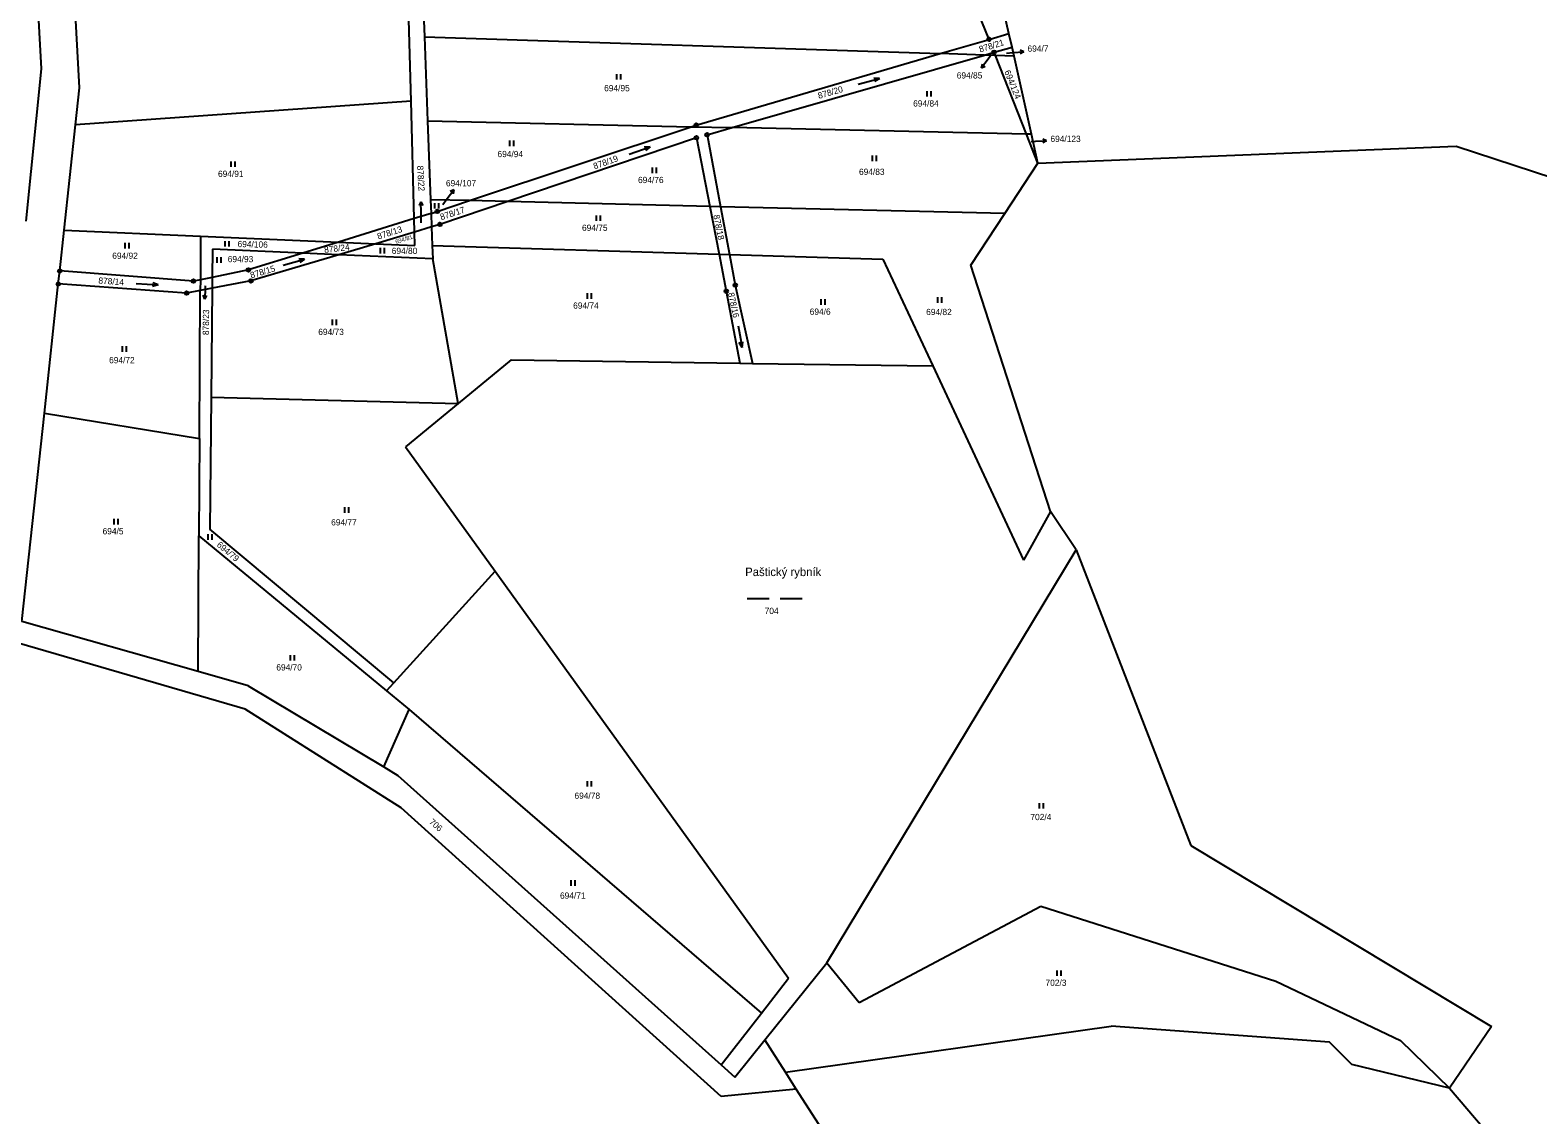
# Model space of a CAD drawing. Extents: x -791032 to -787751, y -1106872 to -1104403.
# Drawn here: x -789595.2 to -789185.3, y -1106556.6 to -1106261.6 of the extents above; entities that cross this region are included whole.
import ezdxf

# ---------------------------------------------------------------- set-up
doc = ezdxf.new("R2010")
doc.units = 0
for name, color, linetype in [('Komunikace', 7, 'Continuous'), ('Vrstva 1', 7, 'Continuous'), ('Vrstva 14', 7, 'Continuous'), ('Vrstva 16', 7, 'Continuous'), ('Vrstva 23', 7, 'Continuous'), ('Vrstva 28', 7, 'Continuous'), ('Vrstva 44', 7, 'Continuous')]:
    doc.layers.add(name, color=color, linetype=linetype)

msp = doc.modelspace()

# ---------------------------------------------------------------- linework, layer by layer
at = {"layer": 'Komunikace'}
for p, q in [((-789333.82, -1106268.19), (-789334.73, -1106269.41)), ((-789329.73, -1106267.83), (-789328.04, -1106267.68)), ((-789323.06, -1106291.82), (-789321.89, -1106291.79)), ((-789483.02, -1106308.99), (-789481.8, -1106307.36)), ((-789488.89, -1106314), (-789488.94, -1106311.25)), ((-789547.64, -1106331.08), (-789547.65, -1106331.7))]:
    msp.add_line(p, q, dxfattribs=at)
at = {"layer": 'Vrstva 1'}
for p, q in [((-789592.13, -1106272.11), (-789596.95, -1106186.19)), ((-789491.65, -1106280.87), (-789492.89, -1106234.87)), ((-789581.8, -1106277.28), (-789583.87, -1106238.77)), ((-789488.84, -1106240.8), (-789488, -1106263.4)), ((-789334.52, -1106264.06), (-789342, -1106245.55)), ((-789329.09, -1106262.43), (-789332.79, -1106245.85)), ((-789488, -1106263.4), (-789487.15, -1106286.25)), ((-789488, -1106263.4), (-789347.81, -1106267.95)), ((-789347.81, -1106267.95), (-789334.52, -1106264.06)), ((-789334.52, -1106264.06), (-789329.09, -1106262.43)), ((-789328.25, -1106266.18), (-789329.09, -1106262.43)), ((-789414.13, -1106287.36), (-789347.81, -1106267.95)), ((-789404.39, -1106288.06), (-789335.78, -1106268.34)), ((-789335.78, -1106268.34), (-789347.81, -1106267.95)), ((-789335.78, -1106268.34), (-789333.13, -1106267.58)), ((-789332.79, -1106268.44), (-789335.78, -1106268.34)), ((-789333.13, -1106267.58), (-789328.25, -1106266.18)), ((-789332.79, -1106268.44), (-789333.13, -1106267.58)), ((-789327.71, -1106268.6), (-789332.79, -1106268.44)), ((-789324.34, -1106289.81), (-789332.79, -1106268.44)), ((-789327.71, -1106268.6), (-789328.25, -1106266.18)), ((-789322.97, -1106289.84), (-789327.71, -1106268.6)), ((-789596.25, -1106313.51), (-789592.13, -1106272.11)), ((-789582.88, -1106287.34), (-789581.8, -1106277.28)), ((-789491.65, -1106280.87), (-789582.88, -1106287.34)), ((-789490.79, -1106312.81), (-789491.65, -1106280.87)), ((-789487.15, -1106286.25), (-789415.5, -1106287.82)), ((-789487.15, -1106286.25), (-789486.35, -1106307.68)), ((-789585.97, -1106315.97), (-789582.88, -1106287.34)), ((-789475.72, -1106307.94), (-789415.5, -1106287.82)), ((-789415.5, -1106287.82), (-789414.13, -1106287.36)), ((-789415.5, -1106287.82), (-789404.39, -1106288.06)), ((-789411.18, -1106290.01), (-789404.39, -1106288.06)), ((-789411.18, -1106290.01), (-789407.52, -1106309.59)), ((-789324.34, -1106289.81), (-789404.39, -1106288.06)), ((-789322.97, -1106289.84), (-789324.34, -1106289.81)), ((-789321.21, -1106297.73), (-789324.34, -1106289.81)), ((-789321.21, -1106297.73), (-789322.97, -1106289.84)), ((-789414.07, -1106290.84), (-789465.36, -1106308.19)), ((-789414.07, -1106290.84), (-789410.44, -1106309.52)), ((-789321.21, -1106297.73), (-789207.47, -1106293.12)), ((-789207.47, -1106293.12), (-789147.83, -1106312.66)), ((-789330.23, -1106311.46), (-789321.21, -1106297.73)), ((-789475.72, -1106307.94), (-789486.35, -1106307.68)), ((-789486.35, -1106307.68), (-789486.21, -1106311.44)), ((-789486.21, -1106311.44), (-789484.54, -1106310.88)), ((-789484.54, -1106310.88), (-789475.72, -1106307.94)), ((-789465.36, -1106308.19), (-789483.79, -1106314.42)), ((-789465.36, -1106308.19), (-789475.72, -1106307.94)), ((-789410.44, -1106309.52), (-789465.36, -1106308.19)), ((-789407.52, -1106309.59), (-789410.44, -1106309.52)), ((-789410.44, -1106309.52), (-789407.92, -1106322.5)), ((-789407.52, -1106309.59), (-789405.09, -1106322.58)), ((-789330.23, -1106311.46), (-789407.52, -1106309.59)), ((-789490.79, -1106312.81), (-789511.4, -1106319.2)), ((-789486.21, -1106311.44), (-789490.79, -1106312.81)), ((-789490.69, -1106316.48), (-789490.79, -1106312.81)), ((-789486.21, -1106311.44), (-789486.07, -1106315.1)), ((-789483.79, -1106314.42), (-789486.07, -1106315.1)), ((-789339.43, -1106325.47), (-789330.23, -1106311.46)), ((-789587.17, -1106327.07), (-789585.97, -1106315.97)), ((-789585.97, -1106315.97), (-789548.86, -1106317.58)), ((-789548.86, -1106317.58), (-789548.93, -1106329.45)), ((-789548.86, -1106317.58), (-789511.4, -1106319.2)), ((-789490.69, -1106316.48), (-789501.27, -1106319.64)), ((-789486.07, -1106315.1), (-789490.69, -1106316.48)), ((-789490.6, -1106320.1), (-789490.69, -1106316.48)), ((-789486.07, -1106315.1), (-789485.88, -1106320.17)), ((-789545.66, -1106321.14), (-789545.73, -1106328.8)), ((-789521.11, -1106322.21), (-789545.66, -1106321.14)), ((-789521.11, -1106322.21), (-789535.87, -1106326.78)), ((-789511.32, -1106322.64), (-789535.2, -1106329.76)), ((-789511.4, -1106319.2), (-789521.11, -1106322.21)), ((-789511.32, -1106322.64), (-789521.11, -1106322.21)), ((-789511.4, -1106319.2), (-789501.27, -1106319.64)), ((-789501.27, -1106319.64), (-789511.32, -1106322.64)), ((-789485.75, -1106323.75), (-789511.32, -1106322.64)), ((-789501.27, -1106319.64), (-789490.6, -1106320.1)), ((-789485.88, -1106320.17), (-789485.75, -1106323.75)), ((-789485.88, -1106320.17), (-789407.92, -1106322.5)), ((-789407.92, -1106322.5), (-789405.96, -1106332.56)), ((-789407.92, -1106322.5), (-789405.09, -1106322.58)), ((-789405.09, -1106322.58), (-789363.39, -1106323.83)), ((-789405.09, -1106322.58), (-789403.53, -1106330.9)), ((-789587.55, -1106330.61), (-789587.17, -1106327.07)), ((-789550.81, -1106329.83), (-789587.17, -1106327.07)), ((-789535.87, -1106326.78), (-789545.73, -1106328.8)), ((-789478.82, -1106363.09), (-789485.75, -1106323.75)), ((-789363.39, -1106323.83), (-789349.79, -1106352.91)), ((-789317.83, -1106392.51), (-789339.43, -1106325.47)), ((-789591.34, -1106365.77), (-789587.55, -1106330.61)), ((-789552.69, -1106333.07), (-789587.55, -1106330.61)), ((-789548.93, -1106329.45), (-789550.81, -1106329.83)), ((-789548.93, -1106329.45), (-789548.95, -1106332.36)), ((-789545.73, -1106328.8), (-789548.93, -1106329.45)), ((-789545.73, -1106328.8), (-789545.76, -1106331.76)), ((-789535.2, -1106329.76), (-789545.76, -1106331.76)), ((-789403.53, -1106330.9), (-789398.83, -1106352.21)), ((-789548.95, -1106332.36), (-789552.69, -1106333.07)), ((-789549.18, -1106372.68), (-789548.95, -1106332.36)), ((-789545.76, -1106331.76), (-789548.95, -1106332.36)), ((-789545.76, -1106331.76), (-789546.03, -1106361.42)), ((-789405.96, -1106332.56), (-789402.31, -1106352.16)), ((-789464.4, -1106351.28), (-789478.82, -1106363.09)), ((-789464.4, -1106351.28), (-789402.31, -1106352.16)), ((-789402.31, -1106352.16), (-789398.83, -1106352.21)), ((-789398.83, -1106352.21), (-789349.79, -1106352.91)), ((-789349.79, -1106352.91), (-789325.1, -1106405.78)), ((-789546.03, -1106361.42), (-789546.37, -1106397.29)), ((-789546.03, -1106361.42), (-789478.82, -1106363.09)), ((-789478.82, -1106363.09), (-789493.19, -1106374.87)), ((-789597.44, -1106422.43), (-789591.34, -1106365.77)), ((-789591.34, -1106365.77), (-789549.18, -1106372.68)), ((-789549.18, -1106372.68), (-789549.33, -1106399.08)), ((-789493.19, -1106374.87), (-789468.82, -1106408.7)), ((-789317.83, -1106392.51), (-789325.1, -1106405.78)), ((-789310.81, -1106402.96), (-789317.83, -1106392.51)), ((-789549.55, -1106436.02), (-789549.33, -1106399.08)), ((-789549.33, -1106399.08), (-789498.34, -1106441.3)), ((-789496.32, -1106439.07), (-789546.37, -1106397.29)), ((-789378.63, -1106515.27), (-789310.81, -1106402.96)), ((-789310.81, -1106402.96), (-789279.63, -1106483.36)), ((-789496.32, -1106439.07), (-789468.82, -1106408.7)), ((-789468.82, -1106408.7), (-789389.04, -1106519.44)), ((-789549.55, -1106436.02), (-789597.44, -1106422.43)), ((-789536.76, -1106446.28), (-789598.09, -1106428.43)), ((-789535.95, -1106439.88), (-789549.55, -1106436.02)), ((-789535.95, -1106439.88), (-789499.09, -1106462)), ((-789498.34, -1106441.3), (-789496.32, -1106439.07)), ((-789498.34, -1106441.3), (-789492.19, -1106446.4)), ((-789494.38, -1106473.09), (-789536.76, -1106446.28)), ((-789499.09, -1106462), (-789492.19, -1106446.4)), ((-789492.19, -1106446.4), (-789396.41, -1106528.93)), ((-789499.09, -1106462), (-789495.23, -1106464.32)), ((-789495.23, -1106464.32), (-789407.36, -1106543.01)), ((-789407.33, -1106551.66), (-789494.38, -1106473.09)), ((-789279.63, -1106483.36), (-789197.91, -1106532.62)), ((-789369.84, -1106526.05), (-789320.47, -1106499.9)), ((-789320.47, -1106499.9), (-789256.58, -1106520.24)), ((-789395.48, -1106536.26), (-789378.63, -1106515.27)), ((-789378.63, -1106515.27), (-789369.84, -1106526.05)), ((-789396.41, -1106528.93), (-789389.04, -1106519.44)), ((-789256.58, -1106520.24), (-789222.66, -1106536.38)), ((-789407.36, -1106543.01), (-789396.41, -1106528.93)), ((-789403.6, -1106546.38), (-789395.48, -1106536.26)), ((-789389.86, -1106545.03), (-789395.48, -1106536.26)), ((-789389.86, -1106545.03), (-789301.3, -1106532.47)), ((-789241.95, -1106536.85), (-789301.3, -1106532.47)), ((-789197.91, -1106532.62), (-789209.35, -1106549.33)), ((-789235.91, -1106542.95), (-789241.95, -1106536.85)), ((-789222.66, -1106536.38), (-789209.35, -1106549.33)), ((-789407.36, -1106543.01), (-789403.6, -1106546.38)), ((-789209.35, -1106549.33), (-789235.91, -1106542.95)), ((-789386.91, -1106549.62), (-789389.86, -1106545.03)), ((-789386.91, -1106549.62), (-789407.33, -1106551.66)), ((-789357.95, -1106594.75), (-789386.91, -1106549.62)), ((-789209.35, -1106549.33), (-789191.93, -1106569.78))]:
    msp.add_line(p, q, dxfattribs=at)
at = {"layer": 'Vrstva 16'}
for p, q in [((-789334.73, -1106269.41), (-789336.52, -1106271.817)), ((-789328.04, -1106267.68), (-789325.051, -1106267.418)), ((-789325.051, -1106267.418), (-789326.091, -1106267.007)), ((-789325.051, -1106267.418), (-789326.004, -1106268.003)), ((-789336.52, -1106271.817), (-789336.324, -1106270.716)), ((-789336.52, -1106271.817), (-789335.522, -1106271.313)), ((-789321.89, -1106291.79), (-789318.891, -1106291.71)), ((-789318.891, -1106291.71), (-789319.903, -1106291.237)), ((-789318.891, -1106291.71), (-789319.877, -1106292.237)), ((-789481.8, -1106307.36), (-789480.007, -1106304.954)), ((-789480.007, -1106304.954), (-789481.006, -1106305.457)), ((-789480.007, -1106304.954), (-789480.204, -1106306.054)), ((-789488.997, -1106308.25), (-789489.478, -1106309.259)), ((-789488.94, -1106311.25), (-789488.997, -1106308.25)), ((-789488.997, -1106308.25), (-789488.478, -1106309.24)), ((-789547.716, -1106334.699), (-789548.194, -1106333.688)), ((-789547.65, -1106331.7), (-789547.716, -1106334.699)), ((-789547.716, -1106334.699), (-789547.194, -1106333.71))]:
    msp.add_line(p, q, dxfattribs=at)
at = {"layer": 'Vrstva 23'}
for p, q in [((-789435.75, -1106274.99), (-789435.75, -1106273.49)), ((-789434.75, -1106273.49), (-789434.75, -1106274.99)), ((-789370.08, -1106276.291), (-789364.299, -1106274.688)), ((-789364.299, -1106274.688), (-789365.878, -1106274.607)), ((-789364.299, -1106274.688), (-789365.61, -1106275.57)), ((-789351.32, -1106279.64), (-789351.32, -1106278.14)), ((-789350.32, -1106278.14), (-789350.32, -1106279.64)), ((-789464.79, -1106293.08), (-789464.79, -1106291.58)), ((-789463.79, -1106291.58), (-789463.79, -1106293.08)), ((-789432.351, -1106295.262), (-789426.668, -1106293.337)), ((-789426.668, -1106293.337), (-789428.249, -1106293.345)), ((-789426.668, -1106293.337), (-789427.928, -1106294.292)), ((-789540.52, -1106298.78), (-789540.52, -1106297.28)), ((-789539.52, -1106297.28), (-789539.52, -1106298.78)), ((-789366.23, -1106297.2), (-789366.23, -1106295.7)), ((-789365.23, -1106295.7), (-789365.23, -1106297.2)), ((-789426.04, -1106300.46), (-789426.04, -1106298.96)), ((-789425.04, -1106298.96), (-789425.04, -1106300.46)), ((-789485.23, -1106310.08), (-789485.23, -1106308.58)), ((-789484.23, -1106308.58), (-789484.23, -1106310.08)), ((-789441.26, -1106313.46), (-789441.26, -1106311.96)), ((-789440.26, -1106311.96), (-789440.26, -1106313.46)), ((-789542.17, -1106320.44), (-789542.17, -1106318.94)), ((-789541.17, -1106318.94), (-789541.17, -1106320.44)), ((-789569.38, -1106320.95), (-789569.38, -1106319.45)), ((-789568.38, -1106319.45), (-789568.38, -1106320.95)), ((-789499.94, -1106322.3), (-789499.94, -1106320.8)), ((-789498.94, -1106320.8), (-789498.94, -1106322.3)), ((-789544.33, -1106324.85), (-789544.33, -1106323.35)), ((-789543.33, -1106323.35), (-789543.33, -1106324.85)), ((-789526.397, -1106325.484), (-789520.622, -1106323.855)), ((-789520.622, -1106323.855), (-789522.202, -1106323.781)), ((-789520.622, -1106323.855), (-789521.93, -1106324.743)), ((-789566.415, -1106330.513), (-789560.424, -1106330.846)), ((-789560.424, -1106330.846), (-789561.95, -1106331.262)), ((-789560.424, -1106330.846), (-789561.894, -1106330.263)), ((-789443.71, -1106334.63), (-789443.71, -1106333.13)), ((-789442.71, -1106333.13), (-789442.71, -1106334.63)), ((-789380.16, -1106336.28), (-789380.16, -1106334.78)), ((-789379.16, -1106334.78), (-789379.16, -1106336.28)), ((-789348.44, -1106335.7), (-789348.44, -1106334.2)), ((-789347.44, -1106334.2), (-789347.44, -1106335.7)), ((-789512.97, -1106341.78), (-789512.97, -1106340.28)), ((-789511.97, -1106340.28), (-789511.97, -1106341.78)), ((-789402.743, -1106341.991), (-789401.636, -1106347.888)), ((-789570.08, -1106349.04), (-789570.08, -1106347.54)), ((-789569.08, -1106347.54), (-789569.08, -1106349.04)), ((-789401.636, -1106347.888), (-789402.404, -1106346.506)), ((-789401.636, -1106347.888), (-789401.421, -1106346.321)), ((-789509.63, -1106392.83), (-789509.63, -1106391.33)), ((-789508.63, -1106391.33), (-789508.63, -1106392.83)), ((-789572.39, -1106396.02), (-789572.39, -1106394.52)), ((-789571.39, -1106394.52), (-789571.39, -1106396.02)), ((-789546.79, -1106400.19), (-789546.79, -1106398.69)), ((-789545.79, -1106398.69), (-789545.79, -1106400.19)), ((-789400.3, -1106416.17), (-789394.3, -1106416.17)), ((-789391.3, -1106416.17), (-789385.3, -1106416.17)), ((-789524.39, -1106433.05), (-789524.39, -1106431.55)), ((-789523.39, -1106431.55), (-789523.39, -1106433.05)), ((-789443.64, -1106467.34), (-789443.64, -1106465.84)), ((-789442.64, -1106465.84), (-789442.64, -1106467.34)), ((-789320.83, -1106473.32), (-789320.83, -1106471.82)), ((-789319.83, -1106471.82), (-789319.83, -1106473.32)), ((-789448.16, -1106494.3), (-789448.16, -1106492.8)), ((-789447.16, -1106492.8), (-789447.16, -1106494.3)), ((-789316.02, -1106518.84), (-789316.02, -1106517.34)), ((-789315.02, -1106517.34), (-789315.02, -1106518.84))]:
    msp.add_line(p, q, dxfattribs=at)
at = {"layer": 'Vrstva 28'}
for centre, radius in [((-789334.52, -1106264.06), 0.5), ((-789334.52, -1106264.06), 0.01), ((-789333.13, -1106267.58), 0.5), ((-789333.13, -1106267.58), 0.01), ((-789414.13, -1106287.36), 0.5), ((-789414.07, -1106290.84), 0.5), ((-789414.13, -1106287.36), 0.01), ((-789411.18, -1106290.01), 0.5), ((-789411.18, -1106290.01), 0.01), ((-789414.07, -1106290.84), 0.01), ((-789484.54, -1106310.88), 0.5), ((-789484.54, -1106310.88), 0.01), ((-789483.79, -1106314.42), 0.5), ((-789483.79, -1106314.42), 0.01), ((-789587.17, -1106327.07), 0.5), ((-789587.17, -1106327.07), 0.01), ((-789535.87, -1106326.78), 0.5), ((-789535.87, -1106326.78), 0.01), ((-789587.55, -1106330.61), 0.5), ((-789587.55, -1106330.61), 0.01), ((-789550.81, -1106329.83), 0.5), ((-789550.81, -1106329.83), 0.01), ((-789535.2, -1106329.76), 0.5), ((-789535.2, -1106329.76), 0.01), ((-789403.53, -1106330.9), 0.5), ((-789403.53, -1106330.9), 0.01), ((-789552.69, -1106333.07), 0.5), ((-789552.69, -1106333.07), 0.01), ((-789405.96, -1106332.56), 0.5), ((-789405.96, -1106332.56), 0.01)]:
    msp.add_circle(centre, radius, dxfattribs=at)

# ---------------------------------------------------------------- texts
at = {"layer": 'Vrstva 14'}
for s, height, rotation, p in [('878/21', 1.7, 16.96275, (-789336.944, -1106267.642)), ('694/124', 1.7, 292.21344, (-789330.41, -1106272.846)), ('878/20', 1.7, 16.12143, (-789380.768, -1106280.261)), ('878/19', 1.7, 19.24245, (-789441.754, -1106299.431)), ('878/17', 1.7, 17.88633, (-789483.449, -1106313.271)), ('878/13', 1.7, 17.88633, (-789500.534, -1106318.55)), ('878/18', 1.7, 281.49273, (-789409.5, -1106311.941)), ('694/106', 1.7, 358.63083, (-789538.837, -1106320.566)), ('694/81', 1.14, 16.95528, (-789495.735, -1106319.692)), ('878/24', 1.7, 6.60978, (-789515.183, -1106322.178)), ('878/15', 1.7, 16.85133, (-789535.091, -1106329.125)), ('878/14', 1.7, 356.05746, (-789576.696, -1106330.493)), ('878/16', 1.7, 282.31506, (-789405.511, -1106333.133)), ('694/79', 1.7, 319.95846, (-789544.624, -1106401.821)), ('706', 1.7, 318.7314, (-789486.87, -1106477.187))]:
    msp.add_text(s, height=height, rotation=rotation, dxfattribs=at).set_placement(p)
for s, height, p in [('694/85', 0.1, (-789334.07, -1106268.19)), ('694/7', 0.1, (-789329.938, -1106267.83)), ('694/95', 1.7, (-789439.152, -1106278.18)), ('694/84', 1.7, (-789355.141, -1106282.34)), ('694/94', 1.7, (-789468.152, -1106296.1)), ('694/123', 0.1, (-789323.339, -1106291.82)), ('694/91', 1.7, (-789544.139, -1106301.48)), ('694/76', 1.7, (-789429.942, -1106303.16)), ('694/83', 1.7, (-789369.866, -1106300.93)), ('694/107', 0.1, (-789483.302, -1106308.99)), ('878/22', 0.1, (-789489.139, -1106314)), ('694/75', 1.7, (-789445.179, -1106316.16)), ('694/92', 1.7, (-789572.886, -1106323.77)), ('694/93', 1.7, (-789541.496, -1106324.68)), ('694/80', 1.7, (-789496.905, -1106322.45)), ('878/23', 0.1, (-789547.89, -1106331.08)), ('694/74', 1.7, (-789447.588, -1106337.33)), ('694/6', 1.7, (-789383.266, -1106338.98)), ('694/82', 1.7, (-789351.605, -1106339.07)), ('694/73', 1.7, (-789516.872, -1106344.48)), ('694/72', 1.7, (-789573.742, -1106352.17)), ('694/5', 1.7, (-789575.512, -1106398.72)), ('694/77', 1.7, (-789513.379, -1106396.29)), ('704', 1.7, (-789395.518, -1106420.39)), ('694/70', 1.7, (-789528.282, -1106435.75)), ('694/78', 1.7, (-789447.212, -1106470.66)), ('702/4', 1.7, (-789323.271, -1106476.46)), ('694/71', 1.7, (-789451.156, -1106497.84)), ('702/3', 1.7, (-789319.156, -1106521.54))]:
    msp.add_text(s, height=height, dxfattribs=at).set_placement(p)
at = {"layer": 'Vrstva 16'}
for s, p in [('694/7', (-789324.05, -1106267.42)), ('694/85', (-789343.294, -1106274.71)), ('694/123', (-789317.81, -1106291.97)), ('694/107', (-789482.17, -1106304.03))]:
    msp.add_text(s, height=1.7, dxfattribs=at).set_placement(p)
for s, rotation, p in [('878/22', 273.57633, (-789490.029, -1106298.464)), ('878/23', 89.43606, (-789546.604, -1106344.519))]:
    msp.add_text(s, height=1.7, rotation=rotation, dxfattribs=at).set_placement(p)
at = {"layer": 'Vrstva 44'}
msp.add_text('Paštický rybník', height=2.3, dxfattribs=at).set_placement((-789400.81, -1106410.07))

doc.saveas('drawing.dxf')
